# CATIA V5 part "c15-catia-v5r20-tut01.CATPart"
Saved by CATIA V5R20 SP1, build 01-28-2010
Part number: Part1
Bounding box of the stored display mesh (mm): x -21 to 122, y 0 to 45, z -43 to 1
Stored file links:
  D:\v5_r20\psrt_files_downloaded\c15-catia-v5r20-prt\c15-catia-v5r20-tut01.CATPart
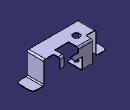
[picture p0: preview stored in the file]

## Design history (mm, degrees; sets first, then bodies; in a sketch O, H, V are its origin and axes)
SheetMetalParameters1: Thickness 1, BendRadius 2, KFactor 0.400515 {= log(min(100,max(20*SheetMetalParameters1.BendRadius,SheetMetalParameters1.Thickness)/SheetMetalParameters1.Thickness))/log(100)/2}, ReliefRadialLength 1, ReliefAxialLength 2, MinimumBendRadius 0
Body1 (main body)
  Sketch1 on xy-plane, origin (0, 0, 0), H (1, 0, 0), V (0, 1, 0)
    line L1 (0, 0) -> (101, 0)
    line L2 (101, 0) -> (101, 32)
    line L3 (101, 32) -> (82, 32)
    line L4 (82, 32) -> (82, 44)
    line L5 (82, 44) -> (74, 44)
    line L6 (74, 44) -> (74, 26)
    line L7 (74, 26) -> (47, 26)
    line L8 (47, 26) -> (47, 44)
    point P8 (47, 44)
    line L9 (47, 44) -> (20, 44)
    line L10 (20, 44) -> (20, 32)
    point P10 (20, 32)
    line L11 (20, 32) -> (0, 32)
    point P11 (0, 32)
    line L12 (0, 32) -> (0, 0)
    length L1 = 101
    length L2 = 32
    length L3 = 19
    length L5 = 8
    distance L1 L5 = 44
    distance L7 L1 = 26
    length L11 = 20
    length L9 = 27
    horizontal: L1 H, L3 H, L5 H, L7 H, L9 H, L11 H
    vertical: L2 V, L4 V, L6 V, L8 V, L10 V, L12 V
    coincidence: P8 L5, P10 L3, P11 V
  Wall1: Thickness 1, Profile Sketch1
  Flange1: Angle 90, Length 44, Radius 2, KFacteur 0.400515 {= log(min(100,max(20*Flange1.Radius,SheetMetalParameters1.Thickness)/SheetMetalParameters1.Thickness))/log(100)/2}, Guide edge [face of Wall1 | face of Wall1]
  Flange2: Angle 90, Length 44, Radius 2, KFacteur 0.400515 {= log(min(100,max(20*Flange2.Radius,SheetMetalParameters1.Thickness)/SheetMetalParameters1.Thickness))/log(100)/2}, Guide edge [face of Wall1 | face of Wall1]
  Flange3: Angle 90, Length 22, Radius 2, KFacteur 0.400515 {= log(min(100,max(20*Flange3.Radius,SheetMetalParameters1.Thickness)/SheetMetalParameters1.Thickness))/log(100)/2}, Guide edge [face of Flange2 | face of Flange2]
  Flange4: Angle 90, Length 22, Radius 2, KFacteur 0.400515 {= log(min(100,max(20*Flange4.Radius,SheetMetalParameters1.Thickness)/SheetMetalParameters1.Thickness))/log(100)/2}, Guide edge [face of Flange1 | face of Flange1]
  Sketch2 on face of Wall1, origin (47, 44, 0), H (-1, 0, 0), V (0, 0, 1)
    point P1 (0, 1)
    line L1 (0, 1) -> (0, -8)
    line L2 (0, -8) -> (-13, -8)
    line L3 (-13, -8) -> (-13, -18)
    line L4 (-13, -18) -> (8, -18)
    line L5 (8, -18) -> (8, -42)
    line L6 (8, -42) -> (27, -42)
    line L7 (27, -42) -> (27, 1)
    line L8 (27, 1) -> (0, 1)
    reference projected line E1 (27, 0) -> (27, 1) from edge [face of Wall1 | face of Wall1]
    reference projected line E2 (0, 1) -> (27, 1) from edge [face of Wall1 | face of Wall1]
    length L6 = 19
    length L7 = 43
    length L3 = 10
    distance L4 L8 = 19
    distance L3 L7 = 40
    coincidence: P1 V, L7 E1, L8 E2
    horizontal: L2 H, L4 H, L6 H
    vertical: L3 V, L5 V, L7 V, L1 V
  d_NewWallOnEdge1: NewWallOnEdge_Edge edge [face of Wall1 | face of Wall1], NewWallOnEdge_WallProfile Sketch2, NewWallOnEdge_Length 27, NewWallOnEdge_HeightLimitOffset 0, NewWallOnEdge_WidthOffset1 0, NewWallOnEdge_WidthOffset2 0, NewWallOnEdge_Angle 0, NewWallOnEdge_BendRadiusValue 2 {= SheetMetalParameters1.BendRadius}, NewWallOnEdge_BendTable SheetMetalParameters1, KFacteur 0.400515 {= log(min(100,max(20*d_NewWallOnEdge1.Radius,SheetMetalParameters1.Thickness)/SheetMetalParameters1.Thickness))/log(100)/2}
  Flange5: Angle 90, Length 19, Radius 2, KFacteur 0.400515 {= log(min(100,max(20*Flange5.Radius,SheetMetalParameters1.Thickness)/SheetMetalParameters1.Thickness))/log(100)/2}, Guide edge [face of Wall1 | face of Wall1]
  Flange6: Angle 90, Length 30, Radius 2, KFacteur 0.400515 {= log(min(100,max(20*Flange6.Radius,SheetMetalParameters1.Thickness)/SheetMetalParameters1.Thickness))/log(100)/2}, Guide edge [face of d_NewWallOnEdge1 | face of d_NewWallOnEdge1]
  Sketch3 on face of Wall1, origin (29.3791, 35.4737, 1), H (1, 0, 0), V (0, 1, 0)
    point P1 (-0.3791, -12.4737)
    reference projected line E1 (30.6209, 9.5263) -> (17.6209, 9.5263) from edge [face of d_NewWallOnEdge1 | face of d_NewWallOnEdge1]
    reference projected line E2 (-9.3791, 8.5263) -> (-9.3791, -3.4737) from edge [face of Wall1 | face of Wall1]
    distance P1 E1 = 22
    distance E2 P1 = 9
  Hole1: placed by Sketch3, at (29, 23, 1) direction (0, 0, -1), diameter 13, through (limit type 6)
  Sketch4 on face of Flange6, origin (31.6177, 25.4906, -41), H (1, 0, 0), V (0, 1, 0)
    point P1 (-2.6177, -2.4906)
    reference projected circle E1 centre (-2.6177, -2.4906) radius 6.5 from edge [face of Wall1 | face of Hole1]
    concentricity: P1 E1
  Hole2: placed by Sketch4, at (29, 23, -41) direction (0, 0, -1), diameter 8, through (limit type 6)
  Corner1: CornerChamferEdges (edge [face of Flange3 | face of Flange3]; edge [face of Flange3 | face of Flange3]; edge [face of Flange4 | face of Flange4]; edge [face of Flange4 | face of Flange4]), CornerRadius 7
  Corner2: CornerChamferEdges (edge [face of Wall1 | face of Wall1]; edge [face of Wall1 | face of Wall1]; edge [face of d_NewWallOnEdge1 | face of d_NewWallOnEdge1]; edge [face of Wall1 | face of Wall1]; edge [face of d_NewWallOnEdge1 | face of d_NewWallOnEdge1]; edge [face of Wall1 | face of Wall1]), CornerRadius 2
  Chamfer1: CornerChamferEdges edge [face of d_NewWallOnEdge1 | face of d_NewWallOnEdge1], ChamferAngle 45, ChamferLength1 6, ChamferLength2 0.5, ChamferPropagation 1, ChamferReverse false, ChamferType 1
